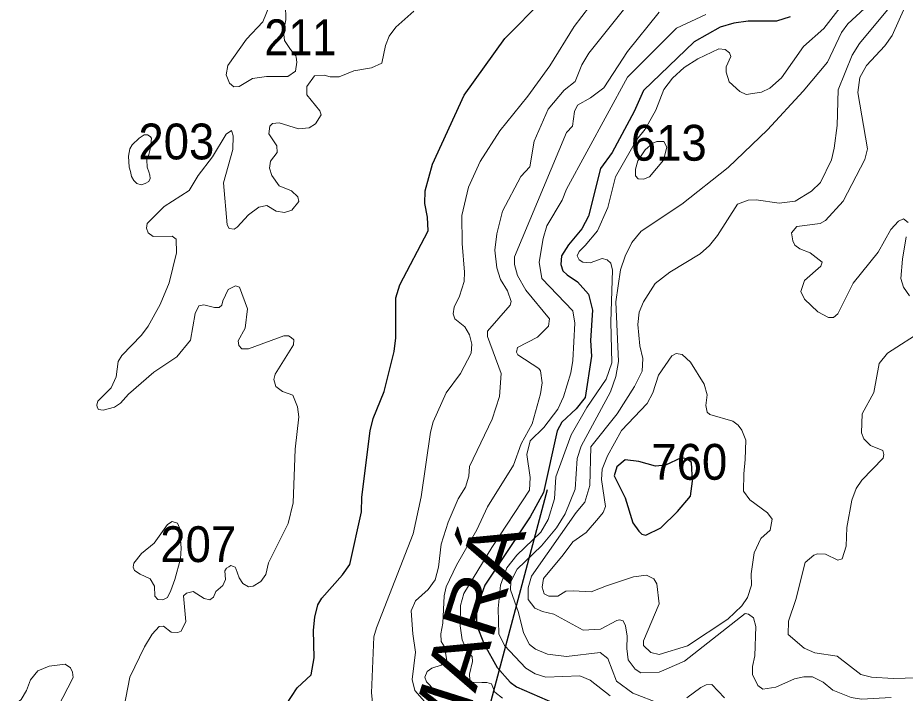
# Model space of a CAD drawing. Extents: x 499.9 to 555.3, y 9281.5 to 9336.8.
# Drawn here: x 538.759 to 542.725, y 9308.08 to 9311.097 of the extents above; entities that cross this region are included whole.
import ezdxf
from ezdxf.enums import TextEntityAlignment as Align

# ---------------------------------------------------------------- set-up
doc = ezdxf.new("R2010")
doc.units = 0
doc.header["$LTSCALE"] = 0.064
for name, color, linetype, lineweight in [('1', 7, 'Continuous', 25), ('2', 7, 'Continuous', 13), ('26', 7, 'Continuous', 25)]:
    doc.layers.add(name, color=color, linetype=linetype, lineweight=lineweight)
doc.layers.add('21', color=7, linetype='Continuous')

msp = doc.modelspace()

# ---------------------------------------------------------------- linework, layer by layer
at = {"layer": '1'}
for points in [[(539.9564, 9308.0264), (540.0068, 9308.1046), (540.0696, 9308.1624), (540.0827, 9308.2383), (540.0798, 9308.3613), (540.0861, 9308.4197), (540.1002, 9308.4746), (540.1174, 9308.5044), (540.2106, 9308.6082), (540.243, 9308.6547), (540.2943, 9308.89), (540.2965, 9308.9553), (540.3331, 9309.2525), (540.3471, 9309.3078), (540.3969, 9309.4276), (540.4409, 9309.6071), (540.4488, 9309.6675), (540.4491, 9309.8466), (540.4668, 9309.9038), (540.5934, 9310.1451), (540.5903, 9310.2062), (540.5779, 9310.2668), (540.5793, 9310.3244), (540.6126, 9310.4435), (540.7545, 9310.7513), (540.9357, 9311.0043), (541.1067, 9311.1786)], [(542.2107, 9311.1016), (542.1494, 9311.0825), (542.0238, 9311.0824), (541.9584, 9311.0726), (541.8981, 9311.0549), (541.782, 9310.9893), (541.5557, 9310.7719), (541.5129, 9310.6779), (541.4159, 9310.4957), (541.3632, 9310.4233), (541.3099, 9310.2107), (541.2791, 9310.1536), (541.2208, 9310.0834), (541.1893, 9310.0334), (541.186, 9309.9943), (541.1955, 9309.9672), (541.2143, 9309.9486), (541.2597, 9309.9178), (541.3101, 9309.8627), (541.3269, 9309.7907), (541.3179, 9309.6557), (541.3224, 9309.5858), (541.2951, 9309.4004), (541.2539, 9309.3507), (541.1901, 9309.2911), (541.1688, 9309.2517), (541.1086, 9308.9771), (541.0481, 9308.8674), (540.8457, 9308.5622), (540.8083, 9308.4585), (540.8083, 9308.385), (540.8437, 9308.2986), (540.9013, 9308.1956), (540.9595, 9308.129), (540.9877, 9308.109), (541.2281, 9308.0046)]]:
    msp.add_lwpolyline(points, dxfattribs=at)
msp.add_lwpolyline([(541.6334, 9308.8186), (541.7074, 9308.891), (541.7648, 9308.9609), (541.7742, 9309.0268), (541.7694, 9309.1108), (541.7485, 9309.1273), (541.7231, 9309.1318), (541.653, 9309.098), (541.6095, 9309.0947), (541.5351, 9309.1155), (541.4729, 9309.1224), (541.4368, 9309.0911), (541.4243, 9309.0517), (541.4733, 9308.9532), (541.5075, 9308.8417), (541.5347, 9308.8044), (541.5476, 9308.7909), (541.5656, 9308.7866)], close=True, dxfattribs=at)
at = {"layer": '2'}
for points in [[(541.0377, 9310.7461), (541.1364, 9310.8819), (541.2451, 9311.0576), (541.3142, 9311.147), (541.4208, 9311.257), (541.4544, 9311.2762)], [(542.5174, 9311.2521), (542.3613, 9311.0485), (542.2708, 9310.9687), (542.1721, 9310.8292), (542.1206, 9310.7821), (542.0826, 9310.764), (542.0143, 9310.7549), (541.9865, 9310.7669), (541.9375, 9310.8114), (541.9245, 9310.8541), (541.9247, 9310.8778), (541.9449, 9310.9245), (541.9393, 9310.94), (541.9205, 9310.9559), (541.8924, 9310.9579), (541.7977, 9310.9141), (541.7368, 9310.8747), (541.6856, 9310.8266), (541.6455, 9310.7761), (541.6103, 9310.6839), (541.5632, 9310.599), (541.5262, 9310.553), (541.4305, 9310.3871), (541.3955, 9310.2489), (541.3504, 9310.1451), (541.2951, 9310.0803), (541.2675, 9310.0531), (541.2582, 9310.0339), (541.2675, 9310.0153), (541.2836, 9310.006), (541.3165, 9310.0029), (541.3705, 9310.0215), (541.3934, 9310.0153), (541.4091, 9310.0012), (541.4162, 9309.9697), (541.4089, 9309.7395), (541.4141, 9309.5559), (541.3887, 9309.4823), (541.3021, 9309.3566), (541.2326, 9309.2341), (541.164, 9309.0463), (541.1575, 9308.9479), (541.1295, 9308.8558), (541.0967, 9308.8)], [(542.5799, 9311.1732), (542.4681, 9311.0706), (542.4397, 9311.0314), (542.3773, 9310.8988), (542.2691, 9310.7698), (542.1094, 9310.596), (541.9331, 9310.4277), (541.7262, 9310.2639), (541.5445, 9310.1438), (541.5026, 9310.0934), (541.473, 9310.0322), (541.4529, 9309.971), (541.4318, 9309.8284), (541.4435, 9309.5614), (541.4313, 9309.4945), (541.4078, 9309.4269), (541.2765, 9309.1833), (541.2585, 9309.1279), (541.2496, 9308.9911), (541.2056, 9308.8813), (541.1669, 9308.819), (541.0998, 9308.7384), (540.9911, 9308.6339), (540.9624, 9308.5792), (540.9614, 9308.5421), (540.9971, 9308.4409), (541.0185, 9308.3505), (541.0451, 9308.2982), (541.0728, 9308.2765), (541.1261, 9308.2542), (541.2105, 9308.2447), (541.3614, 9308.2616), (541.396, 9308.2359), (541.4351, 9308.1343), (541.508, 9308.0805), (541.6307, 9308.0334)], [(540.4484, 9311.0548), (540.5285, 9311.1268)], [(540.6094, 9308.0059), (540.5335, 9308.0921), (540.521, 9308.1409), (540.5365, 9308.2628), (540.5237, 9308.3457), (540.5176, 9308.4484), (540.5367, 9308.4928), (540.5926, 9308.5429), (540.6241, 9308.5861), (540.6397, 9308.6425), (540.6512, 9308.7452), (540.6822, 9308.8445), (540.7275, 9308.9481), (540.7594, 9308.9998), (540.775, 9309.0501), (540.7773, 9309.0924), (540.8786, 9309.3046), (540.9115, 9309.4047), (540.9197, 9309.5083), (540.8581, 9309.6739), (540.858, 9309.6978), (540.9595, 9309.8139), (540.9641, 9309.829), (540.9469, 9309.8776), (540.9157, 9309.9279), (540.8993, 9309.9795), (540.8913, 9310.0592), (540.8992, 9310.1322), (540.9245, 9310.2334), (541.0065, 9310.3875), (541.0469, 9310.4307), (541.0668, 9310.546), (541.1297, 9310.6889), (541.2013, 9310.7737), (541.2497, 9310.8122), (541.2797, 9310.8864), (541.3117, 9310.9395), (541.4653, 9311.1327)], [(542.3107, 9308.1539), (542.272, 9308.1539), (542.2306, 9308.1446), (542.147, 9308.1064), (542.0883, 9308.0985), (542.0666, 9308.1141), (542.0421, 9308.1637), (542.0422, 9308.1992), (542.0531, 9308.2478), (542.0577, 9308.3783), (542.0466, 9308.4163), (542.0248, 9308.4328), (542.0096, 9308.4365), (541.7386, 9308.2234), (541.6252, 9308.1743), (541.5439, 9308.1716), (541.5175, 9308.1871), (541.4868, 9308.2288), (541.4803, 9308.2798), (541.4828, 9308.3342), (541.4755, 9308.3807), (541.4639, 9308.4034), (541.4486, 9308.4073), (541.4358, 9308.4048), (541.3632, 9308.3657), (541.2862, 9308.3615), (541.1547, 9308.4335), (541.1037, 9308.4451), (541.0701, 9308.4598), (541.0405, 9308.498), (541.0404, 9308.5508), (541.0551, 9308.603), (541.2544, 9308.8878), (541.2938, 9308.9339), (541.3149, 9309.0075), (541.32, 9309.1801), (541.4369, 9309.3276), (541.5152, 9309.4495), (541.5492, 9309.5191), (541.5517, 9309.5752), (541.5389, 9309.6312), (541.5299, 9309.7277), (541.5365, 9309.7819), (541.5553, 9309.8284), (541.6075, 9309.9104), (541.6729, 9309.9603), (541.809, 9310.0427), (541.8504, 9310.0792), (541.886, 9310.1244), (541.9759, 9310.2646), (542.0226, 9310.2822), (542.0587, 9310.2833), (542.1622, 9310.2693), (542.2339, 9310.2771), (542.3063, 9310.3221), (542.347, 9310.3609), (542.395, 9310.4626), (542.408, 9310.5142), (542.4208, 9310.6162), (542.4259, 9310.7755), (542.4873, 9310.9305), (542.5212, 9310.9821), (542.6601, 9311.1498)], [(541.4839, 9310.9462), (541.6251, 9311.1222)], [(542.7233, 9311.1443), (542.6663, 9311.0178)], [(541.8338, 9311.1114), (541.703, 9311.0504), (541.4841, 9310.8315), (541.2111, 9310.3312), (541.1917, 9310.2827), (541.1239, 9310.1673), (541.1073, 9310.1112), (541.0888, 9310.0057), (541.1005, 9309.9328), (541.2399, 9309.7877), (541.2477, 9309.7324), (541.2398, 9309.5657), (541.2303, 9309.5115), (541.1985, 9309.4034), (541.1729, 9309.3493), (541.1099, 9309.2666), (541.0493, 9309.2074), (541.0335, 9309.1462), (541.0481, 9309.0441), (541.046, 9308.9876), (540.877, 9308.7305), (540.7525, 9308.5248), (540.7372, 9308.4722), (540.7354, 9308.3805), (540.7444, 9308.319), (540.7638, 9308.2723), (540.7897, 9308.2444), (540.7909, 9308.2212), (540.7777, 9308.1648), (540.7791, 9308.14), (540.7868, 9308.1289), (540.8327, 9308.1284), (540.8552, 9308.1285), (540.8762, 9308.1216), (540.8914, 9308.0843), (540.9258, 9308.0579)], [(540.2603, 9310.8598), (540.3397, 9310.8727), (540.3857, 9310.8941), (540.4015, 9310.9733), (540.419, 9311.0146), (540.4484, 9311.0548)], [(542.6663, 9311.0178), (542.6336, 9310.9721), (542.552, 9310.884), (542.5223, 9310.8307), (542.5133, 9310.7634), (542.5559, 9310.5118)], [(541.2379, 9310.6131), (541.2466, 9310.6779), (541.2603, 9310.7059), (541.3178, 9310.7387), (541.3785, 9310.7838), (541.4839, 9310.9462)], [(539.9413, 9309.4274), (539.9124, 9309.4499), (539.9032, 9309.4813), (539.9098, 9309.5058), (539.9911, 9309.636), (539.9919, 9309.6587), (539.9813, 9309.6692), (539.9693, 9309.6758), (539.9476, 9309.6765), (539.7892, 9309.6184), (539.7601, 9309.6186), (539.747, 9309.6325), (539.7444, 9309.6537), (539.7756, 9309.7113), (539.7851, 9309.7965), (539.7501, 9309.8942), (539.7317, 9309.8996), (539.6994, 9309.8836), (539.6756, 9309.8331), (539.6709, 9309.8139), (539.6592, 9309.8022), (539.6378, 9309.8025), (539.5904, 9309.8152), (539.5685, 9309.8098), (539.5514, 9309.7757), (539.53, 9309.6573), (539.4699, 9309.5832), (539.3667, 9309.5135), (539.2534, 9309.4157), (539.2184, 9309.3763), (539.191, 9309.3574), (539.1398, 9309.3446), (539.1199, 9309.347), (539.1129, 9309.3583), (539.1125, 9309.3679), (539.1161, 9309.3843), (539.1755, 9309.4447), (539.1986, 9309.4939), (539.2068, 9309.5623), (539.2239, 9309.5885), (539.3113, 9309.6793), (539.3411, 9309.7201), (539.3948, 9309.8164), (539.435, 9309.9126), (539.4684, 9310.0471), (539.4661, 9310.1086), (539.4485, 9310.1209), (539.3632, 9310.1204), (539.3417, 9310.1362), (539.3334, 9310.1567), (539.3364, 9310.1774), (539.4128, 9310.2547), (539.525, 9310.3261), (539.5653, 9310.392), (539.6292, 9310.4751), (539.6902, 9310.5772), (539.7139, 9310.5935), (539.7216, 9310.5698), (539.7201, 9310.5082), (539.6783, 9310.3594), (539.6946, 9310.1723), (539.704, 9310.1555), (539.726, 9310.1531), (539.7399, 9310.1618), (539.7901, 9310.2171), (539.8368, 9310.2512), (539.8721, 9310.2583), (539.9143, 9310.2331), (539.9507, 9310.2265), (539.9843, 9310.2374), (540.0144, 9310.2762), (540.0104, 9310.2969), (539.9815, 9310.3236), (539.927, 9310.347), (539.8947, 9310.3921), (539.8834, 9310.4256), (539.8881, 9310.4567), (539.9187, 9310.4948), (539.9166, 9310.5244), (539.8812, 9310.579), (539.8846, 9310.6134), (539.8974, 9310.624), (539.9277, 9310.627), (540.013, 9310.6003), (540.0609, 9310.6048), (540.0887, 9310.6238), (540.1143, 9310.6628), (540.1083, 9310.6812), (540.0502, 9310.7533), (540.0504, 9310.7896), (540.0846, 9310.837), (540.1283, 9310.8405), (540.1552, 9310.8326), (540.1958, 9310.8328), (540.2603, 9310.8598)], [(540.3443, 9308.0392), (540.3391, 9308.0823), (540.3507, 9308.3324), (540.3614, 9308.372), (540.5252, 9308.7921), (540.5617, 9308.957), (540.6031, 9309.2466), (540.6147, 9309.2927), (540.673, 9309.4217), (540.738, 9309.5084), (540.7847, 9309.5983), (540.7877, 9309.6389), (540.7778, 9309.6809), (540.7564, 9309.7161), (540.7119, 9309.7528), (540.7043, 9309.7749), (540.7085, 9309.8039), (540.7332, 9309.8539), (540.7531, 9309.9192), (540.756, 9309.9603), (540.7449, 9310.0885), (540.7434, 9310.2143), (540.7738, 9310.3399), (540.8249, 9310.4548), (540.9137, 9310.5922), (541.0377, 9310.7461)], [(540.7138, 9308.0423), (540.6208, 9308.094), (540.5848, 9308.1311), (540.5782, 9308.1523), (540.5888, 9308.1771), (540.6098, 9308.192), (540.6509, 9308.205), (540.6767, 9308.2258), (540.6652, 9308.2875), (540.651, 9308.3108), (540.6495, 9308.3448), (540.659, 9308.3929), (540.6637, 9308.5145), (540.6731, 9308.5559), (540.7199, 9308.6523), (540.8099, 9308.8093), (540.8576, 9308.9124), (540.9741, 9309.0994), (541.0087, 9309.194), (541.0582, 9309.2828), (541.0951, 9309.4168), (541.1029, 9309.467), (541.0955, 9309.5197), (541.0878, 9309.531), (540.9939, 9309.5922), (540.9873, 9309.6031), (540.992, 9309.6243), (541.0816, 9309.6705), (541.1314, 9309.7202), (541.1345, 9309.7516), (541.0291, 9309.8801), (540.9926, 9309.9463), (540.979, 9309.9954), (540.9789, 9310.0286), (541.2115, 9310.5842), (541.2379, 9310.6131)], [(542.5559, 9310.5118), (542.5451, 9310.4641), (542.4473, 9310.2781), (542.3682, 9310.191), (542.3452, 9310.1784), (542.2409, 9310.1644), (542.2174, 9310.137), (542.222, 9310.1005), (542.2312, 9310.082), (542.2545, 9310.0651), (542.3004, 9310.0474), (542.3535, 9310.0058), (542.3482, 9309.988), (542.2742, 9309.9229), (542.2589, 9309.8745), (542.275, 9309.8398), (542.334, 9309.7833), (542.3827, 9309.7585), (542.405, 9309.7583), (542.4243, 9309.7749), (542.493, 9309.911), (542.6038, 9310.0495), (542.6612, 9310.1513), (542.6952, 9310.1881), (542.7177, 9310.1986), (542.7389, 9310.1822)], [(542.7296, 9310.1187), (542.7122, 9310.0184), (542.7051, 9309.9317), (542.717, 9309.8936), (542.7441, 9309.8555)], [(542.8075, 9309.703), (542.646, 9309.5995), (542.6088, 9309.5527), (542.5849, 9309.4232), (542.5323, 9309.3277), (542.5291, 9309.2438), (542.5405, 9309.2156), (542.5705, 9309.187), (542.6256, 9309.1642), (542.6301, 9309.1461), (542.6258, 9309.1298), (542.5318, 9309.0323), (542.5065, 9308.9951), (542.487, 9308.9417), (542.4637, 9308.8201), (542.4605, 9308.7373), (542.4437, 9308.6805), (542.4241, 9308.6749), (542.3683, 9308.7012), (542.3325, 9308.7029), (542.3159, 9308.6965), (542.2777, 9308.6645), (542.2357, 9308.4989), (542.2031, 9308.4014), (542.2014, 9308.3418), (542.2729, 9308.2814), (542.3215, 9308.2606), (542.4208, 9308.2461), (542.5259, 9308.1637), (542.5749, 9308.1512), (542.6714, 9308.146), (542.8306, 9308.1508)], [(539.9901, 9308.9304), (539.9984, 9309.1702), (540.0142, 9309.315), (540.0095, 9309.3587), (539.9888, 9309.4106), (539.9413, 9309.4274)], [(539.2332, 9308.0131), (539.2597, 9308.1516), (539.3246, 9308.2877), (539.3587, 9308.3433), (539.3905, 9308.3784), (539.4101, 9308.3793), (539.4438, 9308.353), (539.4738, 9308.3515), (539.489, 9308.3568), (539.5094, 9308.4008), (539.4991, 9308.515), (539.5135, 9308.527), (539.5433, 9308.5339), (539.5911, 9308.5027), (539.6176, 9308.4971), (539.6338, 9308.509), (539.6444, 9308.5348), (539.6756, 9308.5612), (539.6875, 9308.5887), (539.6839, 9308.627), (539.6919, 9308.6391), (539.7016, 9308.6445), (539.7113, 9308.6499), (539.7299, 9308.6437), (539.734, 9308.6376), (539.7475, 9308.5959), (539.7642, 9308.5708), (539.7892, 9308.5552), (539.811, 9308.5575), (539.8444, 9308.5791), (539.8672, 9308.6099), (539.8795, 9308.6623), (539.9676, 9308.8374), (539.9901, 9308.9304)], [(541.0967, 9308.8), (540.9898, 9308.6974), (540.9447, 9308.6403), (540.9165, 9308.5621), (540.9051, 9308.4586), (540.9085, 9308.3459)], [(540.9085, 9308.3459), (540.9337, 9308.2925), (541.0298, 9308.1918), (541.0706, 9308.1672), (541.119, 9308.1525), (541.2703, 9308.1579), (541.3163, 9308.1379), (541.407, 9308.0681)], [(538.7095, 9308.0004), (538.7733, 9308.0513), (538.7983, 9308.092), (538.8149, 9308.1402), (538.8479, 9308.1808), (538.899, 9308.2005), (538.9711, 9308.2095), (538.9947, 9308.1934), (539.0027, 9308.1745), (539.0064, 9308.15), (538.9369, 9308.0148), (538.9356, 9307.9854), (538.9602, 9307.9524), (538.9607, 9307.9247), (538.9415, 9307.8771), (538.897, 9307.8252), (538.8876, 9307.7574), (538.9003, 9307.7251), (538.9047, 9307.6835), (538.8492, 9307.6227), (538.8136, 9307.6258), (538.7202, 9307.6509)], [(542.662, 9308.0615), (542.529, 9308.0537), (542.4838, 9308.0603), (542.4018, 9308.0942), (542.358, 9308.1288), (542.3107, 9308.1539)], [(541.7492, 9308.0591), (541.8113, 9308.1061), (541.8359, 9308.1172), (541.8609, 9308.1189), (541.918, 9308.0601)]]:
    msp.add_lwpolyline(points, dxfattribs=at)
for points in [[(539.8535, 9311.0789), (539.8901, 9311.1668), (539.9089, 9311.1883), (539.9348, 9311.1901), (539.9505, 9311.1742), (539.9557, 9311.1565), (539.9573, 9311.0877), (539.9463, 9311.0357), (539.9509, 9310.9951), (539.9773, 9310.9555), (540.0015, 9310.9274), (540.0035, 9310.9207), (540.0066, 9310.8986), (539.9999, 9310.8584), (539.966, 9310.8343), (539.8711, 9310.8341), (539.8074, 9310.8263), (539.7477, 9310.7901), (539.7242, 9310.7886), (539.7054, 9310.8047), (539.6899, 9310.8421), (539.6983, 9310.8842), (539.7815, 9311.0011)], [(539.2631, 9310.4104), (539.2669, 9310.3876), (539.2768, 9310.3701), (539.2905, 9310.3564), (539.3103, 9310.3503), (539.3278, 9310.3564), (539.3445, 9310.3663), (539.3499, 9310.3784), (539.3491, 9310.3937), (539.3445, 9310.4089), (539.3377, 9310.4302), (539.3362, 9310.4622), (539.3438, 9310.4865), (539.3514, 9310.5155), (539.356, 9310.5589), (539.3499, 9310.5672), (539.3392, 9310.5741), (539.324, 9310.5748), (539.3019, 9310.5596), (539.2699, 9310.5299), (539.2593, 9310.5109), (539.2532, 9310.4789), (539.2562, 9310.4302)], [(541.5814, 9310.3869), (541.5554, 9310.3754), (541.5318, 9310.3782), (541.5191, 9310.3914), (541.5193, 9310.4209), (541.5294, 9310.4584), (541.5627, 9310.5072), (541.5967, 9310.5368), (541.6153, 9310.5447), (541.6464, 9310.5442), (541.6597, 9310.5189), (541.6451, 9310.461)], [(541.7515, 9308.2915), (541.9319, 9308.4102), (541.9946, 9308.4703), (542.0204, 9308.5078), (542.0386, 9308.5631), (542.0358, 9308.6126), (542.0503, 9308.707), (542.08, 9308.7708), (542.121, 9308.8077), (542.1307, 9308.8573), (542.1092, 9308.8854), (542.0305, 9308.9445), (542.0026, 9308.9824), (542.0043, 9309.0604), (542.0101, 9309.1237), (542.0128, 9309.2108), (541.9948, 9309.2552), (541.9777, 9309.2779), (541.9543, 9309.2949), (541.8519, 9309.3252), (541.8393, 9309.3356), (541.8337, 9309.3659), (541.8397, 9309.4129), (541.8258, 9309.4598), (541.7655, 9309.5586), (541.7278, 9309.5927), (541.7015, 9309.5972), (541.6814, 9309.5875), (541.6223, 9309.5009), (541.5964, 9309.4224), (541.5724, 9309.3748), (541.4575, 9309.253), (541.394, 9309.14), (541.3711, 9309.0811), (541.3675, 9309.0351), (541.3853, 9308.9142), (541.3748, 9308.8872), (541.3538, 9308.8617), (541.2993, 9308.7974), (541.2398, 9308.7562), (541.1961, 9308.6978), (541.1084, 9308.5928), (541.1017, 9308.5534), (541.1111, 9308.5246), (541.1329, 9308.5131), (541.1721, 9308.5141), (541.2075, 9308.5357), (541.2415, 9308.5371), (541.3216, 9308.5325), (541.3895, 9308.5602), (541.5113, 9308.5997), (541.5693, 9308.6067), (541.6009, 9308.5915), (541.6151, 9308.5682), (541.625, 9308.4794), (541.5554, 9308.3138), (541.5556, 9308.2937), (541.5877, 9308.2614), (541.6251, 9308.2531)], [(539.3697, 9308.5576), (539.3504, 9308.5912), (539.3053, 9308.6118), (539.2808, 9308.6286), (539.2743, 9308.6427), (539.2782, 9308.6608), (539.3117, 9308.7046), (539.3677, 9308.7503), (539.4281, 9308.834), (539.4492, 9308.8477), (539.4729, 9308.84), (539.4819, 9308.8181), (539.4885, 9308.7284), (539.4865, 9308.6808), (539.4613, 9308.5886), (539.4428, 9308.5391), (539.4278, 9308.507), (539.4069, 9308.4966), (539.385, 9308.499), (539.372, 9308.5135)]]:
    msp.add_lwpolyline(points, close=True, dxfattribs=at)
at = {"layer": '26'}
msp.add_lwpolyline([(539.9921, 9305.7242), (540.3162, 9306.3604), (540.5083, 9306.8286), (540.7844, 9307.7109), (541.1265, 9308.9893)], dxfattribs=at)

# ---------------------------------------------------------------- texts
at = {"layer": '21'}
for s, width, p in [('211', 0.9, (539.861, 9310.9298)), ('203', 0.95, (539.2979, 9310.4644)), ('613', 0.95, (541.4987, 9310.4586)), ('760', 0.95, (541.5906, 9309.0335)), ('207', 0.95, (539.3956, 9308.6658))]:
    msp.add_text(s, height=0.16, dxfattribs=dict(at, width=width)).set_placement(p)
at = {"layer": '26', "width": 1.15}
msp.add_text('SERRA CAMARÁ', height=0.24, rotation=72.451, dxfattribs=at).set_placement((540.5873, 9307.393), align=Align.CENTER)

doc.saveas('drawing.dxf')
